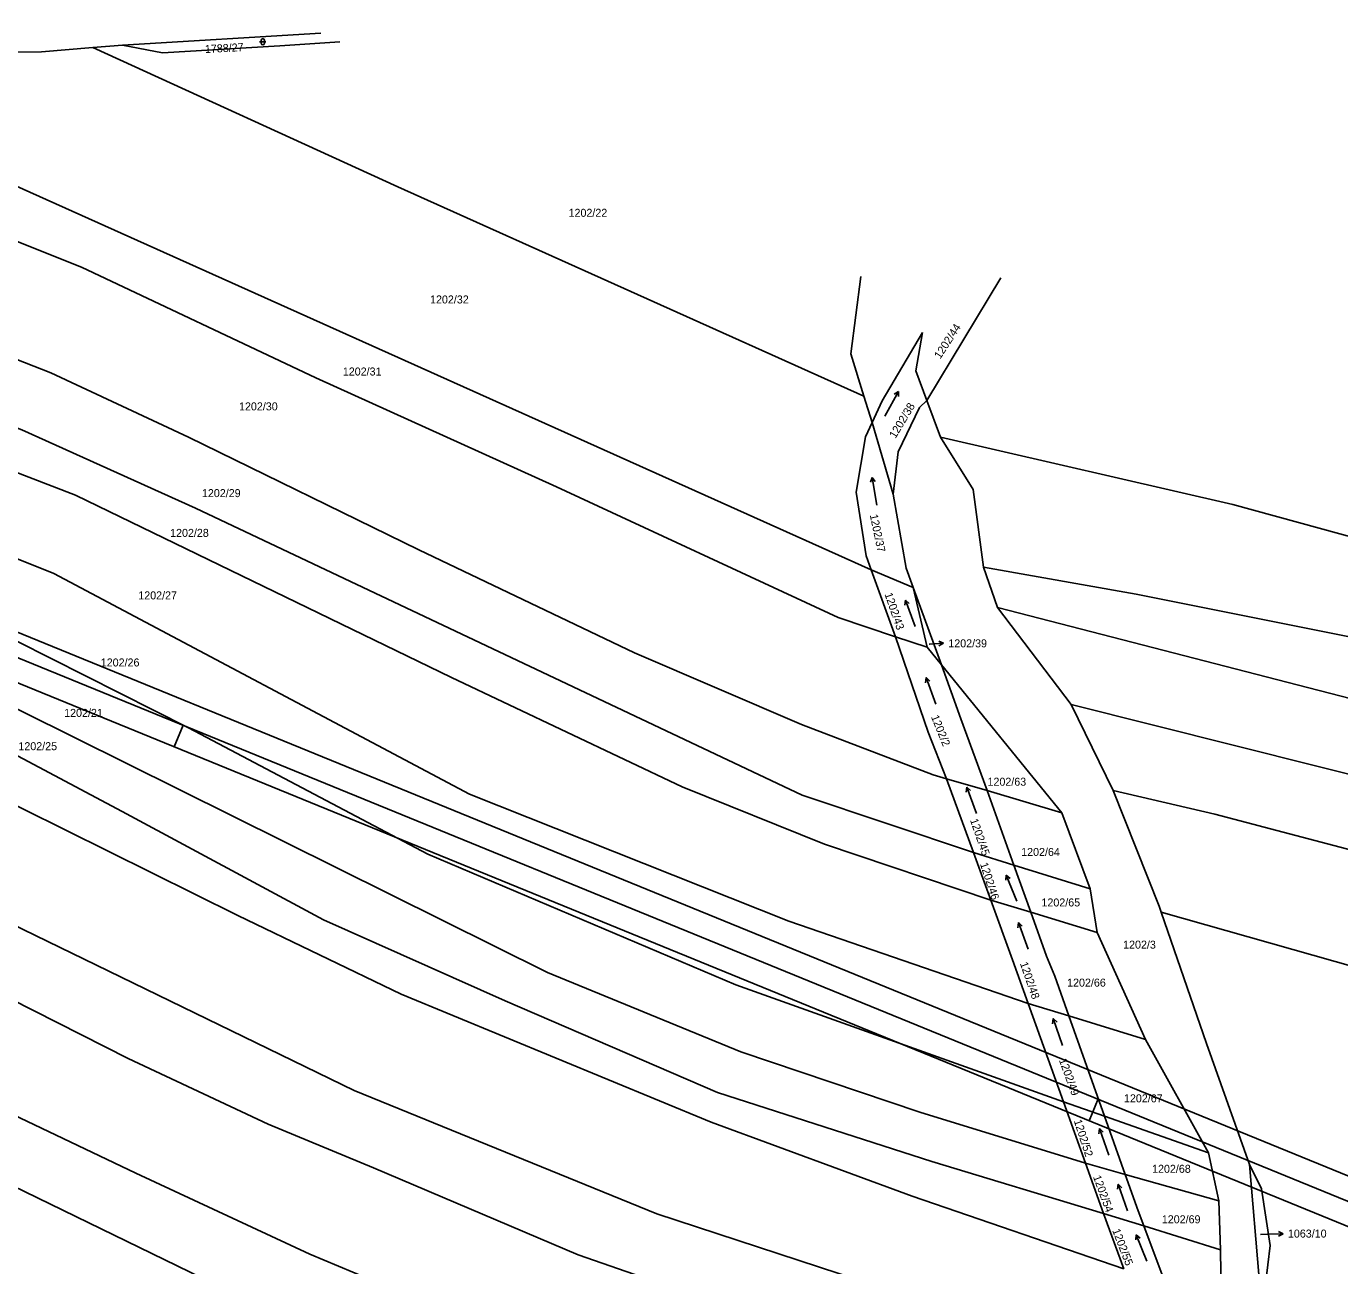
# Model space of a CAD drawing. Extents: x -779330 to -774454, y -1144748 to -1142831.
# Drawn here: x -776332 to -776053, y -1144119.5 to -1143856.1 of the extents above; entities that cross this region are included whole.
import ezdxf

# ---------------------------------------------------------------- set-up
doc = ezdxf.new("R2010")
doc.units = 0
for name, color, linetype in [('Hranice parcel', 7, 'Continuous'), ('Parcelní čísla', 7, 'Continuous'), ('Pop  PČ popisy', 7, 'Continuous'), ('Vrstva 1', 7, 'Continuous'), ('Značky kultur', 7, 'Continuous')]:
    doc.layers.add(name, color=color, linetype=linetype)

msp = doc.modelspace()

# ---------------------------------------------------------------- linework, layer by layer
at = {"layer": 'Hranice parcel'}
for p, q in [((-776311.57, -1143860.13), (-776269.47, -1143857.59)), ((-776317.92, -1143860.64), (-776311.57, -1143860.13)), ((-776125, -1143909.52), (-776140.68, -1143935.59)), ((-776154.06, -1143934.69), (-776152.34, -1143940.3)), ((-776140.68, -1143935.59), (-776137.78, -1143943.38)), ((-776147.85, -1143955.5), (-776152.34, -1143940.3)), ((-776147.38, -1143985.8), (-776152.51, -1143971.59)), ((-776152.51, -1143971.59), (-776143.59, -1143975.32)), ((-776125.72, -1143979.61), (-776128.66, -1143971.04)), ((-776143.59, -1143975.32), (-776137.59, -1143991.79)), ((-776143.59, -1143975.32), (-776140.65, -1143988.03)), ((-776110.04, -1144000.19), (-776125.72, -1143979.61)), ((-776140.65, -1143988.03), (-776147.38, -1143985.8)), ((-776137.59, -1143991.79), (-776140.65, -1143988.03)), ((-776112, -1144023.24), (-776137.59, -1143991.79)), ((-776101.12, -1144018.49), (-776110.04, -1144000.19)), ((-776136.5, -1144016), (-776127.87, -1144018.5)), ((-776130.8, -1144031.65), (-776136.5, -1144016)), ((-776127.87, -1144018.5), (-776112, -1144023.24)), ((-776122.22, -1144034.32), (-776127.87, -1144018.5)), ((-776112, -1144023.24), (-776106.01, -1144039.37)), ((-776127.12, -1144041.75), (-776130.8, -1144031.65)), ((-776130.8, -1144031.65), (-776122.22, -1144034.32)), ((-776118.65, -1144044.33), (-776122.22, -1144034.32)), ((-776122.22, -1144034.32), (-776106.01, -1144039.37)), ((-776106.01, -1144039.37), (-776104.49, -1144048.64)), ((-776127.12, -1144041.75), (-776118.65, -1144044.33)), ((-776118.65, -1144044.33), (-776104.49, -1144048.64)), ((-776104.49, -1144048.64), (-776094.23, -1144071.36)), ((-776111.68, -1144084.62), (-776119.18, -1144063.71)), ((-776119.18, -1144063.71), (-776110.52, -1144066.36)), ((-776102.95, -1144087.69), (-776110.52, -1144066.36)), ((-776110.52, -1144066.36), (-776094.23, -1144071.36)), ((-776094.23, -1144071.36), (-776080.9, -1144095.44)), ((-776107.01, -1144097.64), (-776111.68, -1144084.62)), ((-776111.68, -1144084.62), (-776102.95, -1144087.69)), ((-776098.57, -1144100.04), (-776102.95, -1144087.69)), ((-776102.95, -1144087.69), (-776080.9, -1144095.44)), ((-776080.9, -1144095.44), (-776078.68, -1144105.69)), ((-776103.17, -1144108.34), (-776107.01, -1144097.64)), ((-776107.01, -1144097.64), (-776098.57, -1144100.04)), ((-776098.57, -1144100.04), (-776078.68, -1144105.69)), ((-776078.68, -1144105.69), (-776078.33, -1144116.06)), ((-776098.85, -1144120.12), (-776103.17, -1144108.34)), ((-776103.17, -1144108.34), (-776094.62, -1144111)), ((-776090.1, -1144123.08), (-776094.62, -1144111)), ((-776094.62, -1144111), (-776078.33, -1144116.06)), ((-776078.33, -1144116.06), (-776078.14, -1144127.15))]:
    msp.add_line(p, q, dxfattribs=at)
for points in [[(-776396.99, -1143862.27), (-776328.8, -1143861.5), (-776317.92, -1143860.64)], [(-776317.92, -1143860.64), (-776253.1, -1143890.21), (-776154.06, -1143934.69)], [(-776265.4, -1143859.37), (-776278.19, -1143860.27), (-776303.07, -1143861.75), (-776311.57, -1143860.13)], [(-776152.51, -1143971.59), (-776341.75, -1143886.7), (-776396.99, -1143862.27)], [(-776147.38, -1143985.8), (-776159.54, -1143981.75), (-776219.35, -1143953.95), (-776270.48, -1143930.82), (-776320.26, -1143907.26), (-776342.91, -1143898.29), (-776380.21, -1143885.62), (-776419.82, -1143874.06)], [(-776130.8, -1144031.65), (-776167.18, -1144019.46), (-776296.05, -1143958.5), (-776332.97, -1143941.86), (-776361.98, -1143930.46), (-776408.9, -1143915.72), (-776494.43, -1143891.48), (-776517.13, -1143883.53)], [(-776127.12, -1144041.75), (-776162.43, -1144029.85), (-776192.7, -1144017.69), (-776241.68, -1143994.5), (-776321.54, -1143955.7), (-776383.3, -1143931.9), (-776418.7, -1143920.93), (-776489.84, -1143902.44), (-776518.46, -1143894.36), (-776535.81, -1143887.79)], [(-776119.18, -1144063.71), (-776170, -1144046.22), (-776237.87, -1144019.26), (-776326.2, -1143972.4), (-776378, -1143951.65), (-776436.08, -1143933.84), (-776517.12, -1143911.82), (-776566.02, -1143893.46)], [(-776111.68, -1144084.62), (-776181.26, -1144059.74), (-776246.74, -1144031.99), (-776297.59, -1144005.18), (-776341.39, -1143983.08), (-776381.58, -1143964.67), (-776441.43, -1143945.4), (-776519.5, -1143926.07), (-776584.9, -1143900.82)], [(-776154.75, -1143909.25), (-776156.83, -1143925.67), (-776154.06, -1143934.69)], [(-776593.79, -1143913.81), (-776553, -1143929.07), (-776527.51, -1143937.51), (-776470.29, -1143952.19), (-776437.66, -1143960.66), (-776390.42, -1143976.01), (-776344.1, -1143996.17), (-776221.27, -1144057.17), (-776180.2, -1144074), (-776142.2, -1144086.85), (-776107.01, -1144097.64)], [(-776360.45, -1143916.55), (-776326.79, -1143929.74), (-776297.56, -1143943.4), (-776248.62, -1143967.36), (-776202.79, -1143989.23), (-776167.32, -1144004.47), (-776139.33, -1144015.17), (-776136.5, -1144016)], [(-776152.34, -1143940.3), (-776150.18, -1143935.65), (-776141.66, -1143921.15)], [(-776140.68, -1143935.59), (-776143.08, -1143929.3), (-776141.66, -1143921.15)], [(-776103.17, -1144108.34), (-776139.62, -1144097.29), (-776185.19, -1144082.67), (-776230.28, -1144063.14), (-776268.85, -1144045.98), (-776311.69, -1144022.93), (-776347.15, -1144004.12), (-776382.3, -1143988.84), (-776427.82, -1143973.66), (-776507.88, -1143951.31), (-776536.14, -1143944), (-776596.43, -1143923.1)], [(-776098.85, -1144120.12), (-776143.82, -1144104.66), (-776186.51, -1144088.97), (-776252.37, -1144061.74), (-776287.1, -1144045.07), (-776351.09, -1144013.34), (-776382, -1143998.69), (-776410.54, -1143987.67), (-776454.04, -1143974.87), (-776495.11, -1143963.98), (-776524.93, -1143955.67), (-776598.61, -1143932.15)], [(-776140.68, -1143935.59), (-776142.24, -1143937.1), (-776146.77, -1143946.52), (-776147.85, -1143955.5)], [(-776152.51, -1143971.59), (-776153.58, -1143968.62), (-776155.73, -1143955.09), (-776153.75, -1143943.33), (-776152.34, -1143940.3)], [(-776128.66, -1143971.04), (-776130.9, -1143954.49), (-776137.78, -1143943.38)], [(-776137.78, -1143943.38), (-776075.71, -1143957.68), (-776020.67, -1143972.76), (-775865.74, -1144016.68)], [(-776147.85, -1143955.5), (-776145.07, -1143971.24), (-776143.59, -1143975.32)], [(-776600.02, -1143957.46), (-776528.66, -1143976.76), (-776457.94, -1143997.05), (-776442.28, -1144001.65), (-776398.64, -1144017.46), (-776351.09, -1144039.08), (-776262.34, -1144082.22), (-776198.07, -1144108.44), (-776142.1, -1144126.74), (-776090.77, -1144146.14)], [(-776599.74, -1143971.88), (-776539.25, -1143987.71), (-776480.91, -1144004.77), (-776433.76, -1144019.99), (-776387.97, -1144037.81), (-776365.6, -1144047.46), (-776310.35, -1144075.44), (-776280.61, -1144089.36), (-776258.25, -1144098.68), (-776214.75, -1144117.12), (-776097.7, -1144157.79)], [(-775870.34, -1144033.05), (-775925.32, -1144016.88), (-775992.79, -1143998.11), (-776037.14, -1143988.6), (-776096.24, -1143976.76), (-776128.66, -1143971.04)], [(-776125.72, -1143979.61), (-775989.03, -1144014.87), (-775874.86, -1144045.2)], [(-776136.5, -1144016), (-776140.42, -1144006.05), (-776147.38, -1143985.8)], [(-776601.27, -1143990.4), (-776527.05, -1144013.4), (-776476.25, -1144029.92), (-776451.83, -1144038), (-776413.3, -1144052.52), (-776382.54, -1144065.64), (-776348.92, -1144080.63), (-776308.77, -1144099.81), (-776271.78, -1144116.96), (-776235.24, -1144132.31), (-776202.98, -1144142.91), (-776103.02, -1144176.77)], [(-776137.59, -1143991.79), (-776133.49, -1144003.28), (-776127.87, -1144018.5)], [(-776110.04, -1144000.19), (-776005.41, -1144026.5), (-775880.93, -1144059.24)], [(-776603.25, -1144004.14), (-776531.61, -1144026.86), (-776500.12, -1144036.38), (-776435.33, -1144057.94), (-776392.95, -1144075.37), (-776356.59, -1144091.91), (-776289.18, -1144124.7), (-776254.94, -1144139.28), (-776198.32, -1144160.66), (-776146.7, -1144178.71), (-776104.57, -1144192.02)], [(-776090.92, -1144044.35), (-776091.37, -1144043.03), (-776101.12, -1144018.49)], [(-776101.12, -1144018.49), (-776079.54, -1144023.47), (-776021.21, -1144038.9), (-775887.88, -1144074.73)], [(-776119.18, -1144063.71), (-776122.49, -1144054.47), (-776127.12, -1144041.75)], [(-776110.52, -1144066.36), (-776113.52, -1144057.92), (-776115.32, -1144053.65), (-776118.65, -1144044.33)], [(-776072.19, -1144097.96), (-776081.33, -1144072.23), (-776090.92, -1144044.35)], [(-776090.92, -1144044.35), (-776030.76, -1144061.4), (-775899.17, -1144097.95)], [(-776076.16, -1144140.25), (-776070.08, -1144122.15), (-776072.19, -1144097.96)], [(-776072.19, -1144097.96), (-776069.64, -1144103.09), (-776067.76, -1144115.13), (-776068.77, -1144123.35)], [(-776094.62, -1144111), (-776095.82, -1144107.8), (-776098.57, -1144100.04)]]:
    msp.add_lwpolyline(points, dxfattribs=at)
at = {"layer": 'Pop  PČ popisy'}
for p, q in [((-776137.15, -1143987.19), (-776138.18, -1143986.75)), ((-776140.15, -1143987.35), (-776140.21, -1143987.35)), ((-776140.15, -1143987.35), (-776137.15, -1143987.19)), ((-776137.15, -1143987.19), (-776138.13, -1143987.75)), ((-776065, -1144112.65), (-776066.02, -1144112.18)), ((-776069.79, -1144112.82), (-776068, -1144112.75)), ((-776068, -1144112.75), (-776065, -1144112.65)), ((-776065, -1144112.65), (-776065.98, -1144113.18))]:
    msp.add_line(p, q, dxfattribs=at)
at = {"layer": 'Vrstva 1'}
for p, q in [((-776300.61, -1144009.19), (-776298.72, -1144004.56)), ((-776106.23, -1144088.65), (-776104.34, -1144084.02))]:
    msp.add_line(p, q, dxfattribs=at)
for points in [[(-775713.68, -1144238.31), (-776879.99, -1143761.57), (-776992.36, -1144036.48), (-775826.05, -1144513.22)], [(-775828.78, -1144506.7), (-776985.84, -1144033.74), (-776877.25, -1143768.09), (-775720.2, -1144241.05)], [(-775726.71, -1144243.78), (-776684.76, -1143852.17), (-776789.57, -1144108.58), (-775831.52, -1144500.19)], [(-775831.52, -1144500.19), (-776789.57, -1144108.58), (-776684.76, -1143852.17), (-775726.71, -1144243.78)]]:
    msp.add_lwpolyline(points, close=True, dxfattribs=at)
at = {"layer": 'Značky kultur'}
for p, q in [((-776282.45, -1143859.37), (-776281.11, -1143859.37)), ((-776282.11, -1143859.03), (-776282.11, -1143859.71)), ((-776281.45, -1143859.71), (-776281.45, -1143859.03)), ((-776149.62, -1143938.91), (-776146.71, -1143933.67)), ((-776146.71, -1143933.67), (-776147.62, -1143934.28)), ((-776146.71, -1143933.67), (-776146.74, -1143934.76)), ((-776152.34, -1143951.94), (-776152.67, -1143952.99)), ((-776151.3, -1143957.85), (-776152.34, -1143951.94)), ((-776152.34, -1143951.94), (-776151.68, -1143952.81)), ((-776145.24, -1143978), (-776145.38, -1143979.09)), ((-776143.19, -1143983.64), (-776145.24, -1143978)), ((-776145.24, -1143978), (-776144.44, -1143978.75)), ((-776140.88, -1143994.49), (-776141.02, -1143995.58)), ((-776138.83, -1144000.13), (-776140.88, -1143994.49)), ((-776140.88, -1143994.49), (-776140.08, -1143995.24)), ((-776132.23, -1144017.75), (-776132.37, -1144018.84)), ((-776130.18, -1144023.39), (-776132.23, -1144017.75)), ((-776132.23, -1144017.75), (-776131.43, -1144018.5)), ((-776123.84, -1144036.45), (-776123.94, -1144037.54)), ((-776121.59, -1144042.01), (-776123.84, -1144036.45)), ((-776123.84, -1144036.45), (-776123.01, -1144037.17)), ((-776121.26, -1144046.55), (-776121.4, -1144047.64)), ((-776119.21, -1144052.19), (-776121.26, -1144046.55)), ((-776121.26, -1144046.55), (-776120.46, -1144047.3)), ((-776113.84, -1144066.95), (-776114, -1144068.04)), ((-776111.89, -1144072.63), (-776113.84, -1144066.95)), ((-776113.84, -1144066.95), (-776113.05, -1144067.72)), ((-776104.02, -1144090.31), (-776104.18, -1144091.4)), ((-776102.07, -1144095.99), (-776104.02, -1144090.31)), ((-776104.02, -1144090.31), (-776103.23, -1144091.07)), ((-776100.04, -1144102.12), (-776100.2, -1144103.21)), ((-776098.09, -1144107.8), (-776100.04, -1144102.12)), ((-776100.04, -1144102.12), (-776099.25, -1144102.89)), ((-776096.21, -1144112.89), (-776096.31, -1144113.98)), ((-776093.96, -1144118.45), (-776096.21, -1144112.89)), ((-776096.21, -1144112.89), (-776095.38, -1144113.61))]:
    msp.add_line(p, q, dxfattribs=at)
for centre, start, end in [((-776281.78, -1143859.04), 0, 180), ((-776281.78, -1143859.71), 180, 359.9879)]:
    msp.add_arc(centre, 0.335, start, end, dxfattribs=at)

# ---------------------------------------------------------------- texts
at = {"layer": 'Parcelní čísla'}
for s, rotation, p in [('1788/27', 3, (-776294.03, -1143861.79)), ('1202/44', 57, (-776137.87, -1143926.91)), ('1202/38', 59, (-776147.38, -1143943.8)), ('1202/37', 282, (-776152.84, -1143959.95)), ('1202/43', 289, (-776149.72, -1143976.75)), ('1202/2', 292, (-776139.85, -1144002.82)), ('1202/45', 289, (-776131.56, -1144024.75)), ('1202/46', 288, (-776129.44, -1144034.07)), ('1202/48', 289, (-776120.96, -1144055.21)), ('1202/49', 290, (-776112.67, -1144075.76)), ('1202/52', 288, (-776109.5, -1144088.67)), ('1202/54', 290, (-776105.42, -1144100.56)), ('1202/55', 291, (-776101.35, -1144111.94))]:
    msp.add_text(s, height=1.7, rotation=rotation, dxfattribs=at).set_placement(p)
for s, p in [('1202/22', (-776216.82, -1143896.58)), ('1202/32', (-776246.25, -1143914.99)), ('1202/31', (-776264.78, -1143930.3)), ('1202/30', (-776286.83, -1143937.71)), ('1202/29', (-776294.71, -1143956.14)), ('1202/28', (-776301.47, -1143964.59)), ('1202/27', (-776308.23, -1143977.87)), ('1202/39', (-776136.15, -1143988.06)), ('1202/26', (-776316.2, -1143992.12)), ('1202/21', (-776323.98, -1144002.84)), ('1202/25', (-776333.7, -1144009.91)), ('1202/63', (-776127.82, -1144017.46)), ('1202/64', (-776120.67, -1144032.39)), ('1202/65', (-776116.36, -1144043.11)), ('1202/3', (-776099.01, -1144052.08)), ('1202/66', (-776110.91, -1144060.15)), ('1202/67', (-776098.83, -1144084.73)), ('1202/68', (-776092.86, -1144099.71)), ('1202/69', (-776090.79, -1144110.43)), ('1063/10', (-776064, -1144113.47))]:
    msp.add_text(s, height=1.7, dxfattribs=at).set_placement(p)

doc.saveas('drawing.dxf')
